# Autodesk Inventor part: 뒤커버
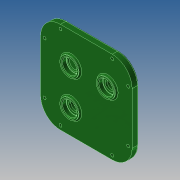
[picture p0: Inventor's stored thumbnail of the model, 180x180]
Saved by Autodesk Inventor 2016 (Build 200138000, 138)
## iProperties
Created: 2016-12
Part Number: 뒤커버
Material: 알루미늄 6061
Document SubType Name: Modeling
Designer: mduedu
Density: 2.71 g/cm^3
Mass: 485.372 g
Surface Area: 454.562 cm^2
Volume: 179.104 cm^3
Appearance: 매끄러움 - 짙은 산림 녹색
Author: mduedu
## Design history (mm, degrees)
sketch "스케치1"
  geometry: L1 (-46, 42)-(-46, -36); L2 (-16, 72)-(62, 72); L3 (92, 42)-(92, -36); L4 (62, -66)-(-16, -66); A1 r 30 centre (-16, -36) between (-46, -36) and (-16, -66); A2 r 30 centre (62, 42) between (92, 42) and (62, 72); A3 r 30 centre (62, -36) between (62, -66) and (92, -36); A4 r 30 centre (-16, 42) between (-16, 72) and (-46, 42); 1 further point
  constraints: 8 end point, 8 point on circle, 8 tangent, 4 centre point, 3 equal radius, 2 perpendicular, 1 horizontal, 1 vertical
  dimensions: "d80" = 30 radius of A2; "d81" = 138 distance between parallel lines of L4 L2; "d82" = 92 distance from line of L3 point (0, 0); "d114" = 46 distance from line of L1 point (0, 0); "d115" = 72 distance from line of L2 point (0, 0)
extrude "돌출1" new body sketch "스케치1" distance "d3" = 10; taper "d4" = 0 deg
sketch "스케치2"
  geometry: C1 r 14 at (0, 26); 1 further point
  constraints: 1 centre point, 1 vertical alignment
  dimensions: "d5" = 28 diameter of C1; "d6" = 26 distance of C1.centre point (0, 0)
extrude "돌출2" join sketch "스케치2" distance "d7" = 3; taper "d8" = 0 deg
sketch "스케치3"
  geometry: C1 r 14 at (0, -28.87); C2 r 14 at (0, 26) reference; C3 r 14 at (54.87, 26); 1 further point
  constraints: 2 centre point, 1 horizontal alignment, 1 vertical alignment
  dimensions: "d9" = 28 diameter of C1; "d69" = 54.87 distance of C1.centre C2.centre; "d83" = 28 diameter of C3; "d84" = 54.87 distance of C3.centre C2.centre
extrude "돌출3" join sketch "스케치3" distance "d11" = 3; taper "d12" = 0 deg
hole "구멍1" diameter "d15" = 22; stored, may be unused: countersink angle "d19" = 90 deg, drill point angle "d21" = 0 deg; dims "d13" = 10, "d14" = 10, "d16" = 6, "d17" = 4, "d18" = 2, "d20" = 7
hole "구멍2" diameter "d24" = 18; stored, may be unused: countersink angle "d28" = 90 deg, drill point angle "d30" = 0 deg; dims "d22" = 10, "d23" = 10, "d25" = 6, "d26" = 4, "d27" = 2, "d29" = 1
hole "구멍3" diameter "d33" = 22; stored, may be unused: countersink angle "d37" = 90 deg, drill point angle "d39" = 0 deg; dims "d31" = 10, "d32" = 10, "d34" = 6, "d35" = 4, "d36" = 2, "d38" = 7
hole "구멍7" diameter "d87" = 22; stored, may be unused: countersink angle "d91" = 90 deg, drill point angle "d93" = 0 deg; dims "d85" = 10, "d86" = 10, "d88" = 6, "d89" = 4, "d90" = 2, "d92" = 7
sketch "스케치4"
  geometry: C1 r 14 at (0, -28.87) reference; C2 r 18 at (0, -28.87); C3 r 14 at (-54.87, 26) reference; C4 r 18 at (-54.87, 26); 1 further point
  constraints: 2 centre point, 2 coincident
  dimensions: "d40" = 36 diameter of C2; "d94" = 36 diameter of C4
extrude "돌출4" join sketch "스케치4" distance "d41" = 4; taper "d42" = 0 deg
hole "구멍4" diameter "d45" = 22; stored, may be unused: countersink angle "d49" = 90 deg, drill point angle "d51" = 0 deg; dims "d43" = 10, "d44" = 10, "d46" = 6, "d47" = 4, "d48" = 2, "d50" = 7
hole "구멍8" diameter "d97" = 22; stored, may be unused: countersink angle "d101" = 90 deg, drill point angle "d103" = 0 deg; dims "d95" = 10, "d96" = 10, "d98" = 6, "d99" = 4, "d100" = 2, "d102" = 7
hole "구멍5" diameter "d54" = 15; stored, may be unused: countersink angle "d58" = 90 deg, drill point angle "d60" = 0 deg; dims "d52" = 10, "d53" = 10, "d55" = 6, "d56" = 4, "d57" = 2, "d59" = 7
hole "구멍9" diameter "d106" = 15; stored, may be unused: countersink angle "d110" = 90 deg, drill point angle "d112" = 0 deg; dims "d104" = 10, "d105" = 10, "d107" = 6, "d108" = 4, "d109" = 2, "d111" = 7
fillet "모깎기1" dims "d61" = 0.3
fillet "모깎기2" dims "d62" = 2
chamfer "모따기1" distance "d63" = 1; stored, may be unused: second distance "d64" = 2, angle "d65" = 45 deg
fillet "모깎기3" dims "d66" = 2
fillet "모깎기4" dims "d67" = 2
fillet "모깎기5" dims "d68" = 2
sketch "스케치5"
  geometry: L1 (-62, 72)-(16, 72) reference; L2 (-92, -36)-(-92, 42) reference; L3 (16, -66)-(-62, -66) reference; L4 (46, 42)-(46, -36) reference; L5 (16, 66)-(-62, 66); L6 (-86, 42)-(-86, -36); L7 (-62, -60)-(16, -60); L8 (40, -36)-(40, 42); A1 r 30 centre (-62, 42) between (-62, 72) and (-92, 42) reference; A2 r 30 centre (-62, -36) between (-92, -36) and (-62, -66) reference; A3 r 30 centre (16, -36) between (16, -66) and (46, -36) reference; A4 r 30 centre (16, 42) between (46, 42) and (16, 72) reference; A5 r 24 centre (-62, 42) between (-62, 66) and (-86, 42); A6 r 24 centre (-62, -36) between (-86, -36) and (-62, -60); A7 r 24 centre (16, -36) between (16, -60) and (40, -36); A8 r 24 centre (16, 42) between (40, 42) and (16, 66)
  constraints: 8 end point, 8 point on circle, 4 centre point, 7 other
  dimensions: "d113" = 6 distance between parallel lines of L6 L2
sketch "스케치6"
  geometry: L1 (16, 66)-(-62, 66) reference; L2 (40, -36)-(40, 42) reference; L3 (-62, -60)-(16, -60) reference; L4 (-86, 42)-(-86, -36) reference; A1 r 24 centre (16, 42) between (40, 42) and (16, 66) reference; A2 r 24 centre (16, -36) between (16, -60) and (40, -36) reference; A3 r 24 centre (-62, -36) between (-86, -36) and (-62, -60) reference; A4 r 24 centre (-62, 42) between (-62, 66) and (-86, 42) reference; 8 further points
  constraints: 8 coincident
hole "구멍6" sketch "스케치6" at (-62, 66), (-86, 42), (-86, -36), (-62, -60), (16, -60), (40, -36), (40, 42), (16, 66) diameter "d71" = 4.5; stored, may be unused: countersink angle "d75" = 90 deg, drill point angle "d77" = 0 deg; dims "d72" = 6, "d73" = 8, "d74" = 4.6, "d76" = 8
node "솔리드1"
